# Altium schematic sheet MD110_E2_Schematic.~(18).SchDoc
size 431 x 279 mm; Date: Not shown in title block; ApprovedBy: Not shown in title block; CheckedBy: Not shown in title block; Author: Not shown in title block; CompanyName: Not shown in title block; Engineer: Not shown in title block; Organization: Not shown in title block; Address1: Not shown in title block; Address2: Not shown in title block; Address3: Not shown in title block; Address4: Not shown in title block; DocumentNumber: 1; Revision: Use project parameter SCH_Rev; SheetNumber: 1; SheetTotal: 2; PageSetup: Record=PageOptions¦CenterHorizontal=True¦CenterVertical=True¦PrintScale=1.00¦XCorrection=1.00¦YCorrection=1.00¦PrintKind=0¦BorderSize=5000000¦LeftOffset=0¦BottomOffset=0¦Orientation=2¦PaperLength=1000¦PaperWidth=1000¦Scale=100¦PaperSource=15¦PrintQuality=600¦MediaType=1¦DitherType=10¦PaperKind=Letter¦PrintScaleMode=1
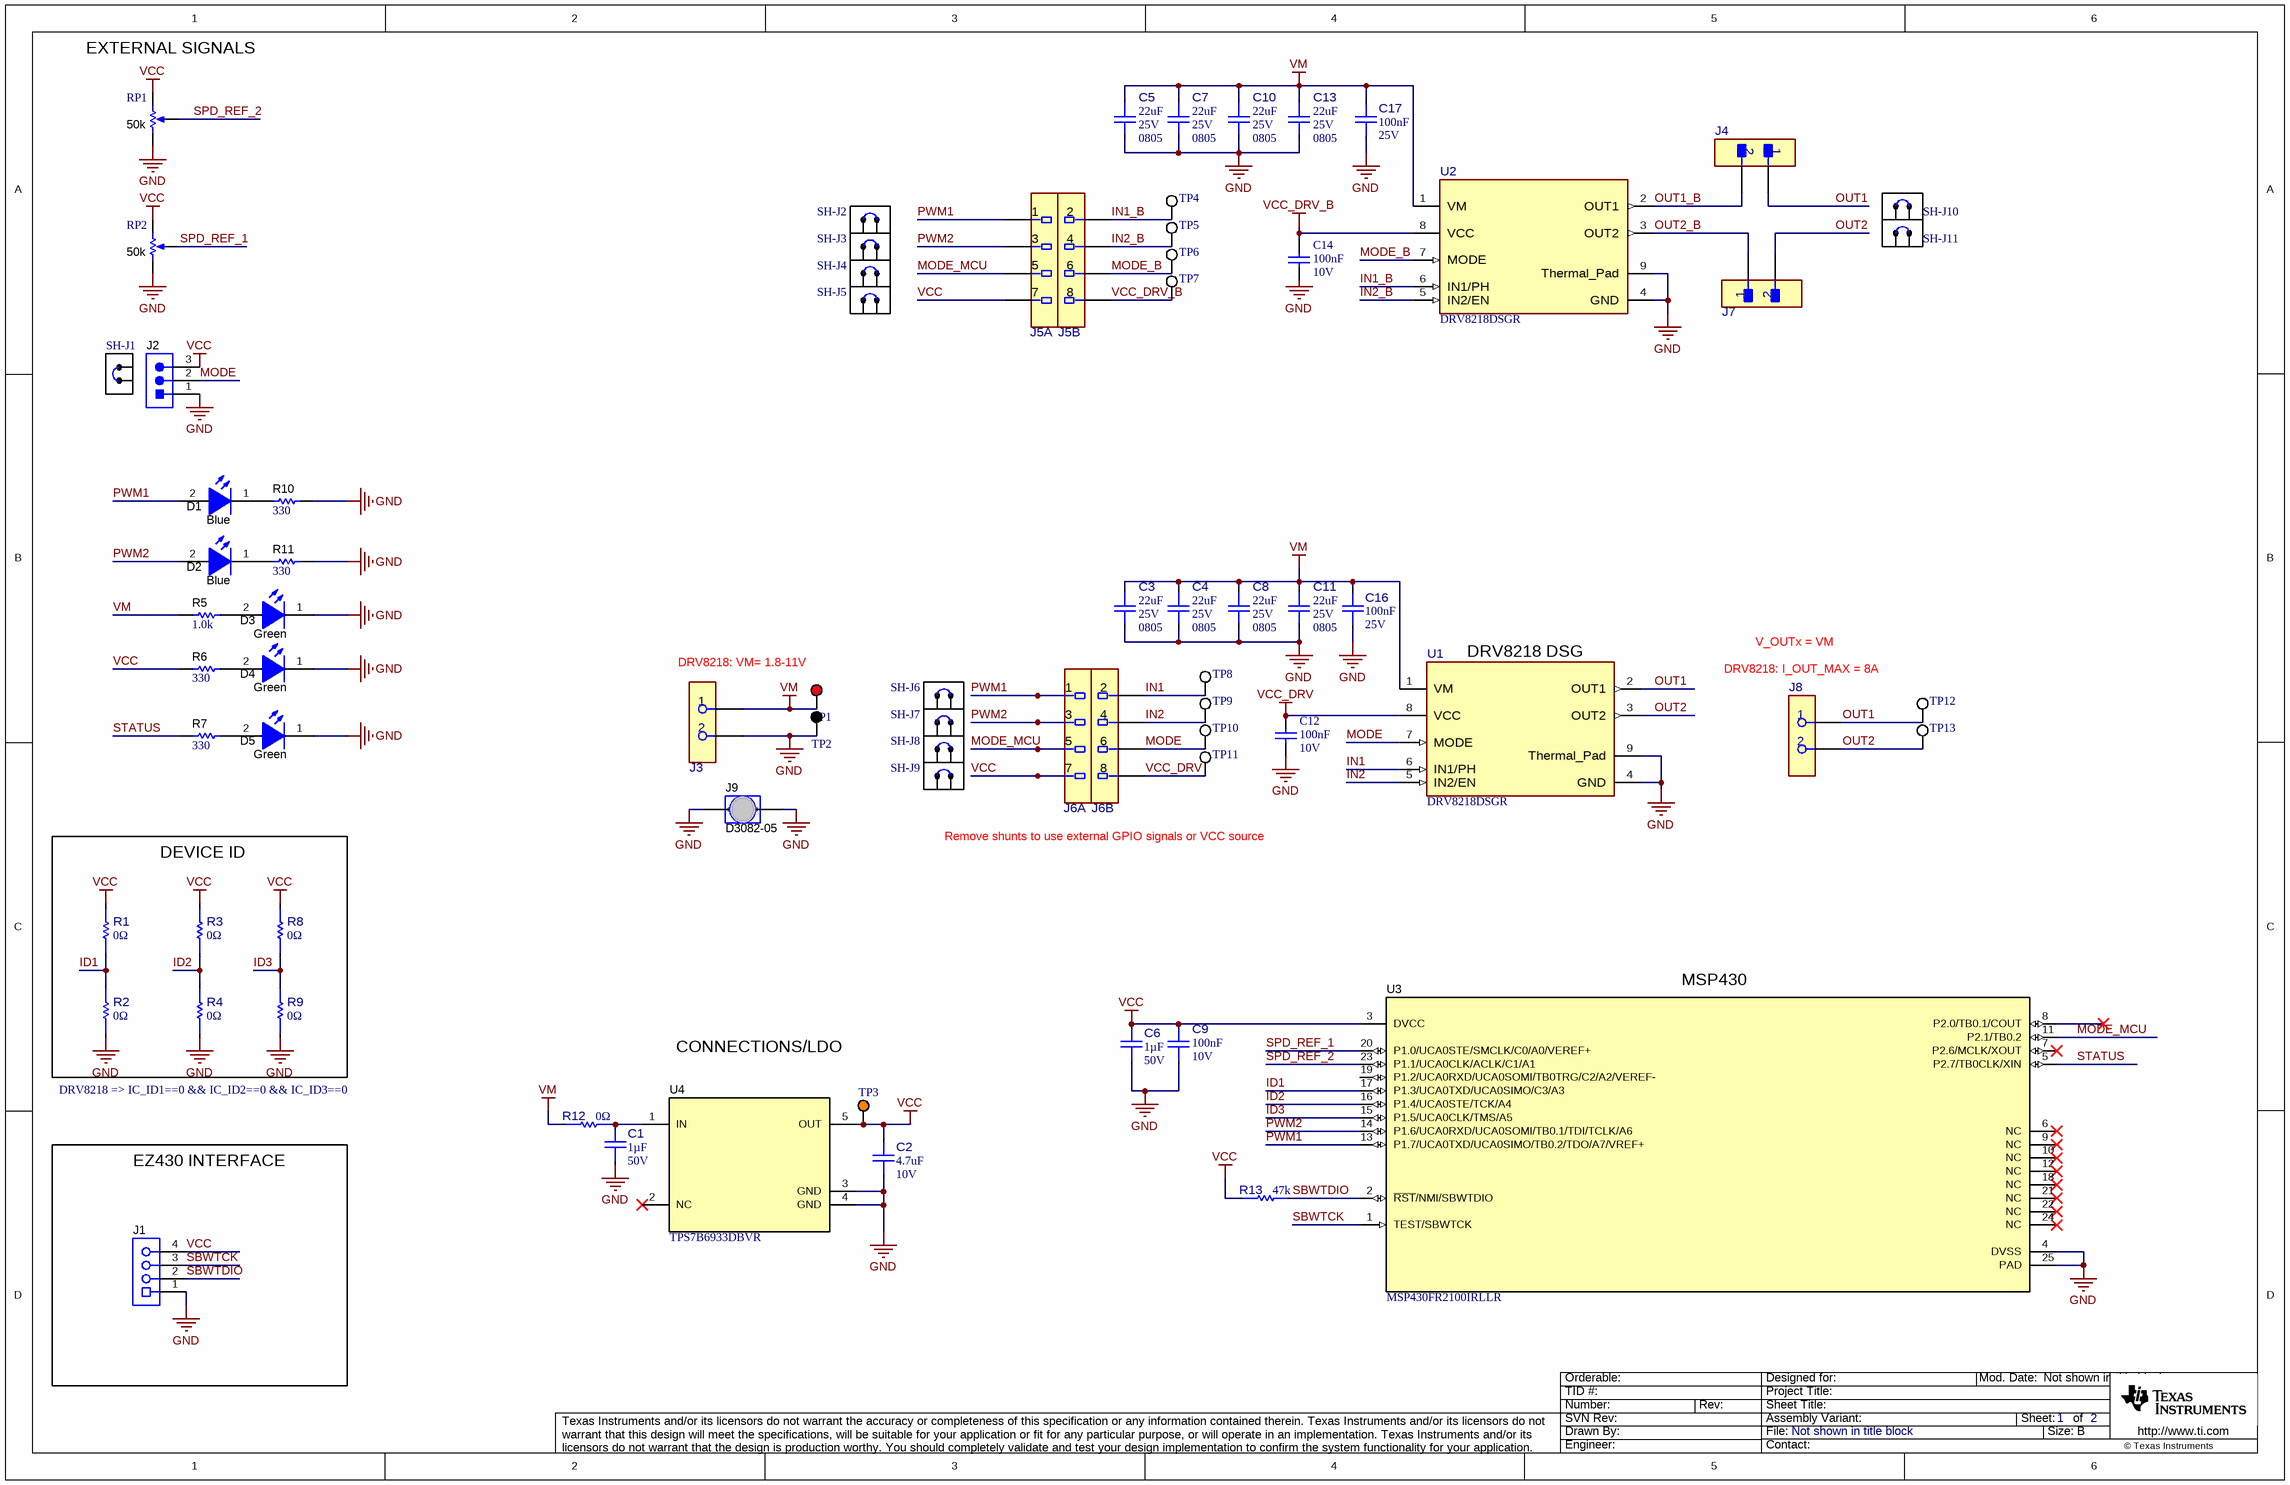
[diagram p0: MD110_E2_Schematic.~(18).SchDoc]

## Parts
C1  Cap_F: 1µF  VDC_V: 50V  [FP-885012206126_0603-MFG]  (hidden comment: 885012206126)
C2  ValueDisplayed: 4.7uF  VDC_V: 10V  [FP-885012106012_0603-MFG]  (hidden comment: 885012106012)
C3  PackageReference: 0805  ValueDisplayed: 22uF  VDC_V: 25V  [FP-885012107019_0805-MFG]  (hidden comment: 885012107019)
C4  PackageReference: 0805  ValueDisplayed: 22uF  VDC_V: 25V  [FP-885012107019_0805-MFG]  (hidden comment: 885012107019)
C5  PackageReference: 0805  ValueDisplayed: 22uF  VDC_V: 25V  [FP-885012107019_0805-MFG]  (hidden comment: 885012107019)
C6  Cap_F: 1µF  VDC_V: 50V  [FP-885012206126_0603-MFG]  (hidden comment: 885012206126)
C7  PackageReference: 0805  ValueDisplayed: 22uF  VDC_V: 25V  [FP-885012107019_0805-MFG]  (hidden comment: 885012107019)
C8  PackageReference: 0805  ValueDisplayed: 22uF  VDC_V: 25V  [FP-885012107019_0805-MFG]  (hidden comment: 885012107019)
C9  value 100nF  VDC_V: 10V  [FP-885012205018_0402-MFG]  (hidden comment: 885012205018)
C10  PackageReference: 0805  ValueDisplayed: 22uF  VDC_V: 25V  [FP-885012107019_0805-MFG]  (hidden comment: 885012107019)
C11  PackageReference: 0805  ValueDisplayed: 22uF  VDC_V: 25V  [FP-885012107019_0805-MFG]  (hidden comment: 885012107019)
C12  Cap_F: 100nF  Rated Voltage (DC): 10V  [WCAP-CSGP_0402_L1W0.5H0.5]  (hidden comment: 885012205018)
C13  PackageReference: 0805  ValueDisplayed: 22uF  VDC_V: 25V  [FP-885012107019_0805-MFG]  (hidden comment: 885012107019)
C14  Cap_F: 100nF  Rated Voltage (DC): 10V  [WCAP-CSGP_0402_L1W0.5H0.5]  (hidden comment: 885012205018)
C16  ValueDisplayed: 100nF  VDC_V: 25V  [FP-885012205085_0402-MFG]  (hidden comment: 885012205085)
C17  ValueDisplayed: 100nF  VDC_V: 25V  [FP-885012205085_0402-MFG]  (hidden comment: 885012205085)
D1  value Blue  [WL-SMCW_Blue]  (hidden comment: 150060BS75000)
D2  value Blue  [WL-SMCW_Blue]  (hidden comment: 150060BS75000)
D3  value Green  [WL-SMCW_GREEN]  (hidden comment: 150060VS75000)
D4  value Green  [WL-SMCW_GREEN]  (hidden comment: 150060VS75000)
D5  value Green  [WL-SMCW_GREEN]  (hidden comment: 150060VS75000)
J1  851-43-004-20-001000  [CONN_851-43-004-20-001000]  (value not drawn)
J2  61300311121  [WURTH_61300311121]  (value not drawn)
J3  691236510002  [FP-691236510002_HHR2-MFG]  (value not drawn)
J4  PH1-02-UA  [FP-PH1-02-UA_HDR2-MFG]  (value not drawn)
J5  61300821121  [FP-61300821121_HDR8-MFG]  (value not drawn)  (parts A,B of 2)
J6  61300821121  [FP-61300821121_HDR8-MFG]  (value not drawn)  (parts A,B of 2)
J7  PH1-02-UA  [FP-PH1-02-UA_HDR2-MFG]  (value not drawn)
J8  691236510002  [FP-691236510002_HHR2-MFG]  (value not drawn)
J9  D3082-05  [Harwin_D3082-05]
R1  value 0Ω  [FP-CR0402-10W-000T_0402-IPC_A]  (hidden comment: CR0402-10W-000T)
R2  value 0Ω  [FP-CR0402-10W-000T_0402-IPC_A]  (hidden comment: CR0402-10W-000T)
R3  value 0Ω  [FP-CR0402-10W-000T_0402-IPC_A]  (hidden comment: CR0402-10W-000T)
R4  value 0Ω  [FP-CR0402-10W-000T_0402-IPC_A]  (hidden comment: CR0402-10W-000T)
R5  ValueDisplayed: 1.0k  [0603]  (hidden comment: ESR03EZPJ102)
R6  ValueDisplayed: 330  [0402]  (hidden comment: CRCW0402330RFKED)
R7  ValueDisplayed: 330  [0402]  (hidden comment: CRCW0402330RFKED)
R8  value 0Ω  [FP-CR0402-10W-000T_0402-IPC_A]  (hidden comment: CR0402-10W-000T)
R9  value 0Ω  [FP-CR0402-10W-000T_0402-IPC_A]  (hidden comment: CR0402-10W-000T)
R10  ValueDisplayed: 330  [0402]  (hidden comment: CRCW0402330RFKED)
R11  ValueDisplayed: 330  [0402]  (hidden comment: CRCW0402330RFKED)
R12  value 0Ω  [FP-ERJ-3GEY0R00V_0603-MFG]  (hidden comment: ERJ-3GEY0R00V)
R13  Res_ohm: 47k  [FP-ERJ-2GEJ473X_0402-MFG]  (hidden comment: ERJ-2GEJ473X)
RP1  value 50k  [Bourns_3352T]  (hidden comment: 3352T-1-503LF)
RP2  value 50k  [Bourns_3352T]  (hidden comment: 3352T-1-503LF)
SH-J1  60900213421  [Wurth_60900213421]  (value not drawn)
SH-J2  60900213421  [Wurth_60900213421]  (value not drawn)
SH-J3  60900213421  [Wurth_60900213421]  (value not drawn)
SH-J4  60900213421  [Wurth_60900213421]  (value not drawn)
SH-J5  60900213421  [Wurth_60900213421]  (value not drawn)
SH-J6  60900213421  [Wurth_60900213421]  (value not drawn)
SH-J7  60900213421  [Wurth_60900213421]  (value not drawn)
SH-J8  60900213421  [Wurth_60900213421]  (value not drawn)
SH-J9  60900213421  [Wurth_60900213421]  (value not drawn)
SH-J10  60900213421  [Wurth_60900213421]  (value not drawn)
SH-J11  60900213421  [Wurth_60900213421]  (value not drawn)
TP1  5010  [Keystone5010]  (value not drawn)
TP2  5011  [Keystone5011]  (value not drawn)
TP3  5013  [Keystone5013]  (value not drawn)
TP4  5002  [Keystone5002]  (value not drawn)
TP5  5002  [Keystone5002]  (value not drawn)
TP6  5002  [Keystone5002]  (value not drawn)
TP7  5002  [Keystone5002]  (value not drawn)
TP8  5012  [Keystone5012]  (value not drawn)
TP9  5012  [Keystone5012]  (value not drawn)
TP10  5012  [Keystone5012]  (value not drawn)
TP11  5012  [Keystone5012]  (value not drawn)
TP12  5012  [Keystone5012]  (value not drawn)
TP13  5012  [Keystone5012]  (value not drawn)
U1  DRV8218DSGR  [DSG0008A-MFG]
U2  DRV8218DSGR  [DSG0008A-MFG]
U3  MSP430FR2100IRLLR  [RLL0024A]
U4  TPS7B6933DBVR  [DBV0005A_N]

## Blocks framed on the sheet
DEVICE ID: R1-R4 R8 R9
EZ430 INTERFACE: J1

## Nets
GND: C1.1 C2.1 C3.2 C4.2 C5.2 C6.1 C7.2 C8.2 C9.1 C10.2 C11.2 C12.1 C13.2 C16.1 C17.1 D3.1(K) D4.1(K) D5.1(K) J1.1 J2.1 J3.2 J9.1 J9.2 R2.1 R4.1 R9.1 R10.2 R11.2 RP1.1(CCW) RP2.1(CCW) TP2.1 U1.4(GND) U1.9(Thermal_Pad) U2.4(GND) U2.9(Thermal_Pad) U3.4(DVSS) U3.25(PAD) U4.3(GND) U4.4(GND)
VCC: C2.2 C6.2 C9.2 J1.4 J2.3 J5.7 J6.7 R1.2 R3.2 R6.1 R8.2 R13.1 RP1.3(CW) RP2.3(CW) TP3.1 U3.3(DVCC) U4.5(OUT)
VCC_DRV: C12.2 J6.8 TP11.1 U1.8(VCC)
VCC_DRV_B: C14.2 J5.8 TP7.1 U2.8(VCC)
VM: C3.1 C4.1 C5.1 C7.1 C8.1 C10.1 C11.1 C13.1 C16.2 C17.2 J3.1 R5.1 R12.1 TP1.1 U1.1(VM) U2.1(VM)
ID1: R1.1 R2.2 U3.17(P1.3/UCA0TXD/UCA0SIMO/C3/A3)
ID2: R3.1 R4.2 U3.16(P1.4/UCA0STE/TCK/A4)
ID3: R8.1 R9.2 U3.15(P1.5/UCA0CLK/TMS/A5)
IN1: J6.2 TP8.1 U1.6(IN1/PH)
IN1_B: J5.2 TP4.1 U2.6(IN1/PH)
IN2: J6.4 TP9.1 U1.5(IN2/EN)
IN2_B: J5.4 TP5.1 U2.5(IN2/EN)
MODE: J2.2 J6.6 TP10.1 U1.7(MODE)
MODE_B: J5.6 TP6.1 U2.7(MODE)
MODE_MCU: J5.5 J6.5 U3.11(P2.1/TB0.2)
OUT1: J4.1 J8.1 TP12.1 U1.2(OUT1)
OUT1_B: J4.2 U2.2(OUT1)
OUT2: J7.2 J8.2 TP13.1 U1.3(OUT2)
OUT2_B: J7.1 U2.3(OUT2)
PWM1: D1.2(A) J5.1 J6.1 U3.13(P1.7/UCA0TXD/UCA0SIMO/TB0.2/TDO/A7/VREF+)
PWM2: D2.2(A) J5.3 J6.3 U3.14(P1.6/UCA0RXD/UCA0SOMI/TB0.1/TDI/TCLK/A6)
SBWTCK: J1.3 U3.1(TEST/SBWTCK)
SBWTDIO: J1.2 R13.2 U3.2(~{RST}/NMI/SBWTDIO)
SPD_REF_1: RP2.2(WIPER) U3.20(P1.0/UCA0STE/SMCLK/C0/A0/VEREF+)
SPD_REF_2: RP1.2(WIPER) U3.23(P1.1/UCA0CLK/ACLK/C1/A1)
STATUS: R7.1 U3.5(P2.7/TB0CLK/XIN)
NetC1_2: C1.2 R12.2 U4.1(IN)
NetD1_1: D1.1(K) R10.1
NetD2_1: D2.1(K) R11.1
NetD3_2: D3.2(A) R5.2
NetD4_2: D4.2(A) R6.2
NetD5_2: D5.2(A) R7.2

Not connected (* = marked no-connect by the designer): C14 1; U3 6(NC)* 7(P2.6/MCLK/XOUT)* 8(P2.0/TB0.1/COUT)* 9(NC)* 10(NC)* 12(NC)* 18(NC)* 19(P1.2/UCA0RXD/UCA0SOMI/TB0TRG/C2/A2/VEREF-) 21(NC)* 22(NC)* 24(NC)*; U4 2(NC)*

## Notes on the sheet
- (near RP1) EXTERNAL SIGNALS
- DRV8218: VM= 1.8-11V
- (near U1) DRV8218 DSG
- V_OUTx = VM
- DRV8218: I_OUT_MAX = 8A
- Remove shunts to use external GPIO signals or VCC source
- (near U3) MSP430
- DRV8218 => IC_ID1==0 && IC_ID2==0 && IC_ID3==0
- CONNECTIONS/LDO
- Labels drawn without touching a wire or pin: GND

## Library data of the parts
C1 C6 = CMP-0120896-1: 1 µF ±10% 50V Ceramic Capacitor X7R 0603 (1608 Metric); Manufacturer: Wurth Electronics; AEC Qualified: No; SizeZ_mm: 0.95mm; TempCo: 15%; ValueDisplayed: 1uF; Value: 1µF
C2 = CMP-0097305-1: 4.7 µF ±20% 10V Ceramic Capacitor X5R 0603 (1608 Metric); Manufacturer: Wurth Electronics; Cap_F: 4.7µF; Value: 4.7µF; AEC Qualified: No; SizeZ_mm: 0.87mm; TempCo: 15%
C3-C5 C7 C8 C10 C11 C13 = CMP-0124987-1: Ceramic Capacitor 0805 22µF ±20% 25V X5R; Manufacturer: Wurth; AEC Qualified: No; SizeZ_mm: 1.45mm; TempCo: 15%
C9 = CMP-0090362-1: 0.1µF ±10% 10V Ceramic Capacitor X7R 0402 (1005 Metric); Manufacturer: Wurth Electronics; AEC Qualified: No; SizeZ_mm: 0.55mm; ValueDisplayed: 100000pF; TempCo: 15%
C12 C14 = CMP-0119248-1: 0.1µF ±10% 10V Ceramic Capacitor X7R 0402 (1005 Metric); Manufacturer: Wurth Elektronik; Capacitance Tolerance: +/-10%; Case/Size Code: 0402; Dissipation Factor: 5%; Insulation Resistance: 5GOhm; Match Code: WCAP-CSGP; Technical Reference: X7R0402104K010DFCT10000
C16 C17 = CMP-0090365-1: CAP, CERAMIC, 0402, X7R, 100nF, 25V, ±15 %, SMD; Manufacturer: Wurth Electronics; Tolerance_%: 10%; AEC Qualified: No; TempCo: 15%; SizeZ_mm: 0.55mm
D1 D2 = CMP-0002946-3: LED, Blue, SMD; Manufacturer: Wurth Elektronik; Power_TotalModule: 105mW; Angle: 140; Tjmax_C: 85°C; Vf_V: 3.2V; Io_A: 30mA; Value1: 0.105W; Vr_V: 5V; Type: InGaN
D3-D5 = CMP-0002894-2: LED, Green, SMD; Manufacturer: Wurth Elektronik; Type: AlInGaP; Vf_V: 2V; Io_A: 20mA; Value1: W
J1 = CMP-0055060-1: SOCKET .050" GRID SIP 4 POS R/A, TH; Manufacturer: Mill-Max; CompType: Socket Strip; CNHeader: FALSE; CT: TRUE; Gender: Female; Green_Lifecycle: Active; Green_REACh: Passed
J2 = CMP-0054796-4: Header, 2.54 mm, 3x1, Gold, TH; Manufacturer: Wurth Elektronik; Green_Lifecycle: Active; Green_REACh: Passed; CNHeader: TRUE; CT: FALSE
J3 J8 = CMP-0121282-1: 2 Position Wire to Board Terminal Block Horizontal with Board 0.200" (5.08mm) Through Hole; Manufacturer: Wurth Electronics; Current_A: 20A; Row_Count: 1; Voltage_V: 300V; AEC Qualified: No; Conn Gender: Female; Is Female: yes; Max Wire Gauge: 12; Min Wire Gauge: 30; SizeZ_mm: 18.1mm
J4 J7 = CMP-0032636-1: Connector Header Through Hole 2 position 0.100" (2.54mm); Manufacturer: Adam Tech; ContactFinish: Gold,Nickel; Current_A: 3A; Row_Count: 1; Voltage_V: 250V; AEC Qualified: No; Conn Gender: Male; Conn Orientation: Vertical; SizeZ_mm: 0.364inch
J5 J6 = CMP-0087153-1: CONN HEADER VERT 8POS 2.54MM; Manufacturer: Wurth Electronics; Voltage_V: 250V; Row_Count: 2; Current_A: 3A; ContactFinish: Gold
J9 = CMP-0075110-1: 1mm Uninsulated Shorting Plug, 10.16mm spacing, TH; Manufacturer: Harwin; CNHeader: False; Green_Lifecycle: Active; Green_REACh: Passed; CompType: Jumper Wire
R1-R4 R8 R9 = CMP-0094948-1: 0 Ohms Jumper 0.1W, 1/10W Chip Resistor 0402 (1005 Metric) - Thick Film; Manufacturer: Venkel; AEC Qualified: No; VDC_V: 50V; SizeZ_mm: 0.4mm; Res_ohm: 0; Power_W: 100mW
R5 = CMP-0084244-1: RES, 1.0 k, 5%, 0.25 W, AEC-Q200 Grade 0, 0603; Manufacturer: Rohm; Power_W: 250mW; TempCo: 200 ppm/C; SizeAreaWB_mm2: 4.68; Value_Code: 1k00; Value: 1.0k; EIA_Code: E24; Res_ohm: 1k; SizeX_mm: 1.6; SizeY_mm: 0.8; SizeZ_mm: 1; Value2: 0.25W; SizeArea_mm2: 1.28; AEC Qualified: Y; AEC Grade: 0; AEC Category: Q200
R6 R7 R10 R11 = CMP-0078658-2: RES, 330, 1%, 0.063 W, AEC-Q200 Grade 0, 0402; Manufacturer: Vishay-Dale; Power_W: 63mW; TempCo: 100 ppm/C; Value_Code: 330R; Value: 330; SizeX_mm: 1; SizeY_mm: 0.5; SizeZ_mm: 0.6; Value2: 0.063W; AEC Qualified: Y; AEC Grade: 0; AEC Category: Q200
R12 = CMP-0089143-1: 0 Ohms Jumper 0.1W, 1/10W Chip Resistor 0603 (1608 Metric) Automotive AEC-Q200 Thick Film; Manufacturer: Panasonic; SizeZ_mm: 0.55mm; AEC Grade: Grade 0; VDC_V: 75V; TempCo: -100/+600ppm/°C; AEC Qualified: Yes; Power_W: 100mW; Tolerance_%: 5%
R13 = CMP-0122885-1: 47 kOhms ±5% 0.1W, 1/10W Chip Resistor 0402 (1005 Metric) Automotive AEC-Q200 Thick Film; Manufacturer: Panasonic; AEC Grade: Grade 0; AEC Qualified: Yes; Power_W: 100mW; SizeZ_mm: 0.4mm; TempCo: 200ppm/°C; VDC_V: 50V; Value: 47k
RP1 RP2 = CMP-0001777-2: Trimming Potentiometer, 50K, 0.5W, TH; Manufacturer: Bourns; CompType: Trimmer
SH-J1-SH-J11 = CMP-0003761-2: Shunt, 2.54mm, Gold, Black; Manufacturer: Wurth Elektronik
TP1 = CMP-0055147-2: Test Point, Multipurpose, Red, TH; Manufacturer: Keystone Electronics; CT: TRUE; ContactFinish: Silver; Green_Lifecycle: Active; CNHeader: FALSE; Green_REACh: Passed
TP2 = CMP-0055148-2: Test Point, Multipurpose, Black, TH; Manufacturer: Keystone Electronics; CNHeader: FALSE; ContactFinish: Silver; Green_REACh: Passed; Green_Lifecycle: Active; CT: TRUE
TP3 = CMP-0055150-2: Test Point, Multipurpose, Orange, TH; Manufacturer: Keystone Electronics; CT: TRUE; ContactFinish: Silver; Green_REACh: Passed; CNHeader: FALSE; Green_Lifecycle: Active
TP4-TP7 = CMP-0055139-2: Test Point, Miniature, White, TH; Manufacturer: Keystone Electronics; ContactFinish: Silver; Green_REACh: Passed; CT: TRUE; Green_Lifecycle: Active; CNHeader: FALSE
TP8-TP13 = CMP-0055149-2: Test Point, Multipurpose, White, TH; Manufacturer: Keystone Electronics; ContactFinish: Silver; CT: TRUE; CNHeader: FALSE; Green_Lifecycle: Active; Green_REACh: Passed
U1 U2 = CMP-0126978-1: Manufacturer: Texas Instruments; SizeZ_mm: 0.8mm; Standoff Height: 0mm
U3 = CMP-0080370-1: 16 MHz Ultra-Low-Power Microcontroller With 1 KB FRAM, 0.5 KB SRAM, 12 IO, 8 ch 10-bit ADC, RLL0024A (VQFN-24); Manufacturer: Texas Instruments; Alternate PartNumber: MSP430FR2100IRLLT; SizeAreaWB_mm2: 16; SizeArea_mm2: 9; AEC Qualified: N; AEC Category: Q200; SizeZ_mm: 1; SizeY_mm: 3; CompType: IC
U4 = CMP-0077328-2: 40-V Ultralow-Iq Low-Dropout Regulator, DBV0005A (SOT-23-5); Manufacturer: Texas Instruments; SizeArea_mm2: 8.12; CompType: IC; SizeAreaWB_mm2: 14.82; SizeY_mm: 2.9; SizeZ_mm: 1.45; SizeX_mm: 2.8; AEC Category: Q200; AEC Qualified: N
